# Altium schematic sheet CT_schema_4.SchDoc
size 365 x 192 mm
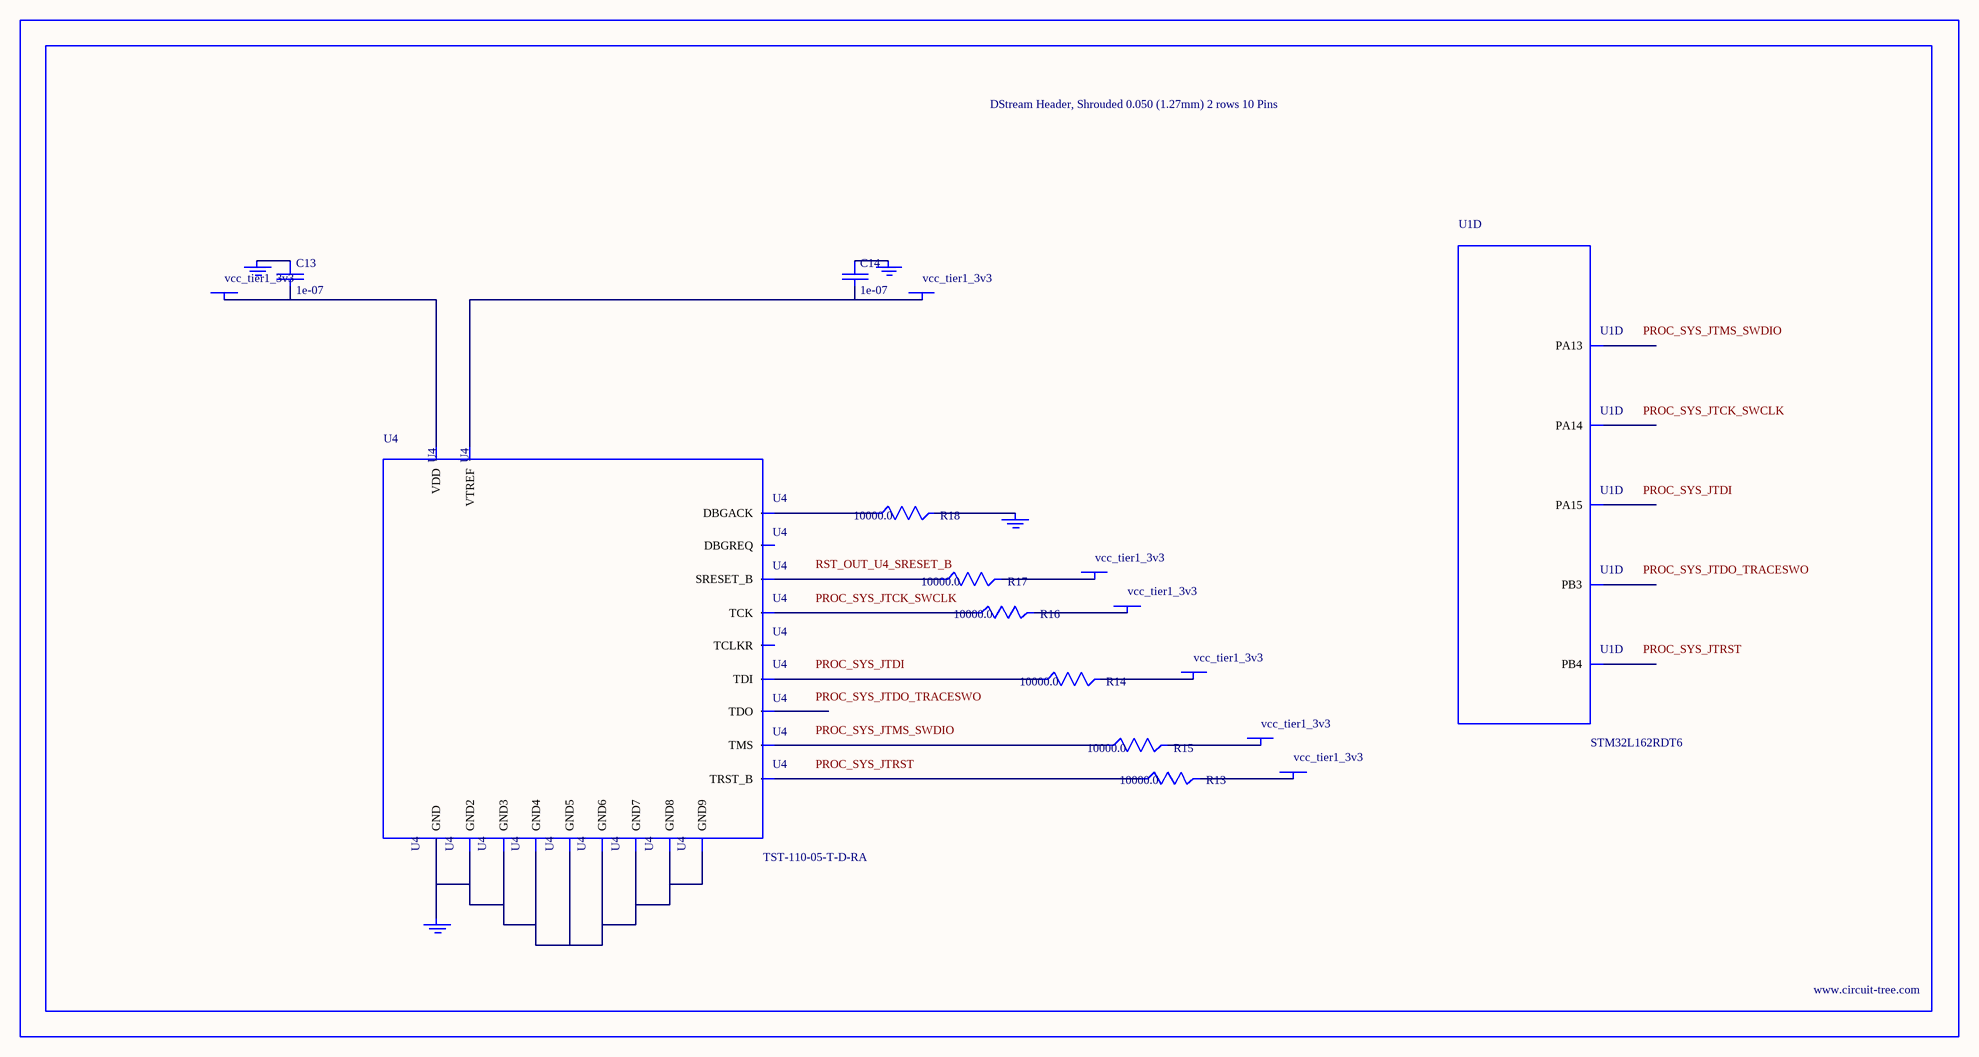
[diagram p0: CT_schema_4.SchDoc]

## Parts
BORDER3  (no value)
C13  1e-07  [C0402]
C14  1e-07  [C0402]
GND_INSTANCE_3_0  (no value)
GND_INSTANCE_3_1  (no value)
GND_INSTANCE_3_2  (no value)
GND_INSTANCE_3_3  (no value)
POWER_INSTANCE_3_0  vcc_tier1_3v3
POWER_INSTANCE_3_1  vcc_tier1_3v3
POWER_INSTANCE_3_2  vcc_tier1_3v3
POWER_INSTANCE_3_3  vcc_tier1_3v3
POWER_INSTANCE_3_4  vcc_tier1_3v3
POWER_INSTANCE_3_5  vcc_tier1_3v3
POWER_INSTANCE_3_6  vcc_tier1_3v3
R13  10000.0  [R0603]
R14  10000.0  [R0603]
R15  10000.0  [R0603]
R16  10000.0  [R0603]
R17  10000.0  [R0603]
R18  10000.0  [R0603]
U1  STM32L162RDT6  [LQFP64]  (part D of 5)
U4  TST-110-05-T-D-RA  [TST-110-05-T-D-RA]

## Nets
NetC13_1: C13.1 GND_INSTANCE_3_1.0(GND)
NetC13_2: C13.2 POWER_INSTANCE_3_1.0(PWR) U4.2(VDD)
NetC14_1: C14.1 GND_INSTANCE_3_0.0(GND)
NetC14_2: C14.2 POWER_INSTANCE_3_0.0(PWR) U4.1(VTREF)
NetGND_INSTANCE_3_2_0: GND_INSTANCE_3_2.0(GND) R18.2
NetGND_INSTANCE_3_3_0: GND_INSTANCE_3_3.0(GND) U4.4(GND) U4.6(GND2) U4.8(GND3) U4.10(GND4) U4.12(GND5) U4.14(GND6) U4.16(GND7) U4.18(GND8) U4.20(GND9)
NetPOWER_INSTANCE_3_2_0: POWER_INSTANCE_3_2.0(PWR) R13.2
NetPOWER_INSTANCE_3_3_0: POWER_INSTANCE_3_3.0(PWR) R14.2
NetPOWER_INSTANCE_3_4_0: POWER_INSTANCE_3_4.0(PWR) R15.2
NetPOWER_INSTANCE_3_5_0: POWER_INSTANCE_3_5.0(PWR) R16.2
NetPOWER_INSTANCE_3_6_0: POWER_INSTANCE_3_6.0(PWR) R17.2
NetR13_1: R13.1 U4.3(TRST_B)
NetR14_1: R14.1 U4.5(TDI)
NetR15_1: R15.1 U4.7(TMS)
NetR16_1: R16.1 U4.9(TCK)
NetR17_1: R17.1 U4.15(SRESET_B)
NetR18_1: R18.1 U4.19(DBGACK)

Not connected (* = marked no-connect by the designer): U1 46(PA13) 49(PA14) 50(PA15) 55(PB3) 56(PB4); U4 11(TCLKR) 13(TDO) 17(DBGREQ)

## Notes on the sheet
- Labels drawn without touching a wire or pin: PROC_SYS_JTCK_SWCLK, PROC_SYS_JTDI, PROC_SYS_JTDO_TRACESWO, PROC_SYS_JTMS_SWDIO, PROC_SYS_JTRST, RST_OUT_U4_SRESET_B

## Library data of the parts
BORDER3 = BORDER_PAGE3
C13 C14 = C0402C104K3RACTU
GND_INSTANCE_3_0-GND_INSTANCE_3_3 = GND
POWER_INSTANCE_3_0-POWER_INSTANCE_3_6 = PWR
R13-R18 = RC0603JR-0710KL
